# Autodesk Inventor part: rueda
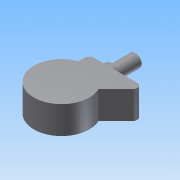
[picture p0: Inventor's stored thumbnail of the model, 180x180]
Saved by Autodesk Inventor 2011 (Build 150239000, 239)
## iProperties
Created: 2020-12
Part Number: rueda
Document SubType Name: Modeling
Designer: PC
Density: 1 g/cm^3
Author: PC
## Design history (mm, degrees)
sketch "Sketch1" dims "d3" = 0
  geometry: L1 (0, 0)-(0, 30); L2 (0, 30)-(30, 30); L3 (30, 30)-(0, 0); L4 (54.142, 40)-(-10, 40); L5 (-10, 40)-(-10, -24.142); L6 (-10, -24.142)-(54.142, 40); C1 r 30 at (0, 0); 3 further points
  constraints: 12 end point, 2 perpendicular, 2 vertical, 1 centre point, 1 coincident, 1 horizontal, 1 tangent, 12 other
  dimensions: "d0" = 60 diameter of C1; "d1" = 45 deg angle of L3 L1; "d2" = 10 distance between parallel lines of L6 L3
extrude "Extrusion1" new body sketch "Sketch1" distance "d4" = 30; taper "d5" = 0 deg
sketch "Sketch2"
  geometry: L1 (64.142, 0)-(64.142, -30) reference; L2 (0, 0)-(0, -30) reference; L3 (0, -15)-(64.142, -15); C1 r 10 at (15, -15); 2 further points
  constraints: 2 end point, 2 midpoint, 1 centre point, 1 coincident, 1 point on line
  dimensions: "d6" = 15 distance from line of point (15, -15) L2; "d7" = 20 diameter of C1
extrude "Extrusion2" join sketch "Sketch2" distance "d8" = 10; taper "d9" = 0 deg
fillet "Fillet1" dims "d10" = 5
sketch "Sketch3"
  geometry: C1 r 10 at (0, 0) reference; C2 r 7 at (0, 0); 1 further point
  constraints: 1 centre point, 1 coincident
  dimensions: "d11" = 14 diameter of C2
extrude "Extrusion3" join sketch "Sketch3" distance "d12" = 25; taper "d13" = 0 deg
body "Solid1"
